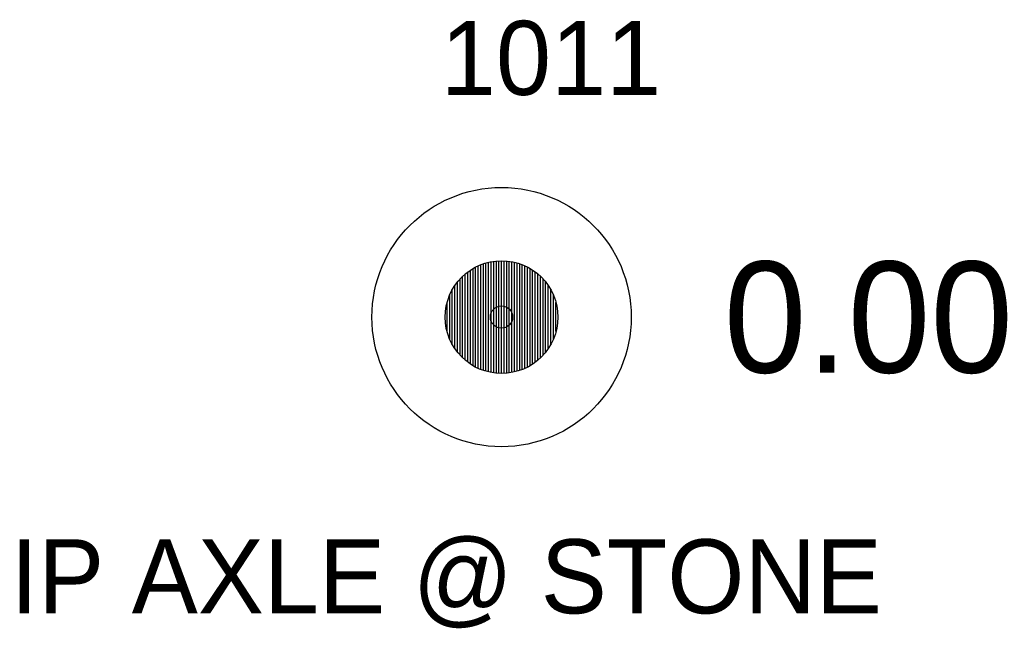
# Model space of a CAD drawing. Extents: x 1393163 to 1398407, y 1072670 to 1074651.
# Drawn here: x 1398094.25 to 1398107.58, y 1074061.18 to 1074069.39 of the extents above; entities that cross this region are included whole.
import ezdxf

# ---------------------------------------------------------------- set-up
doc = ezdxf.new("R2010")
doc.units = 0
for name, color, linetype in [('RD_EX_DV_Prop_txCode', 7, 'Continuous'), ('RD_EX_DV_PropPin', 7, 'Continuous'), ('RD_EX_TX_DV_Prop_ELEV', 7, 'Continuous'), ('RD_SMD_Locator', 7, 'Continuous')]:
    doc.layers.add(name, color=color, linetype=linetype)

msp = doc.modelspace()

# ---------------------------------------------------------------- linework, layer by layer
at = {"layer": 'RD_EX_DV_PropPin'}
for p, q in [((1398100.686, 1074064.619), (1398100.686, 1074066.135)), ((1398100.721, 1074064.617), (1398100.721, 1074066.137)), ((1398100.756, 1074064.616), (1398100.756, 1074066.138)), ((1398100.791, 1074064.617), (1398100.791, 1074066.137)), ((1398100.826, 1074064.619), (1398100.826, 1074066.135)), ((1398100.336, 1074064.742), (1398100.336, 1074066.011)), ((1398100.371, 1074064.721), (1398100.371, 1074066.033)), ((1398100.406, 1074064.701), (1398100.406, 1074066.053)), ((1398100.441, 1074064.684), (1398100.441, 1074066.07)), ((1398100.476, 1074064.669), (1398100.476, 1074066.084)), ((1398100.511, 1074064.656), (1398100.511, 1074066.097)), ((1398100.546, 1074064.645), (1398100.546, 1074066.108)), ((1398100.581, 1074064.636), (1398100.581, 1074066.118)), ((1398100.616, 1074064.629), (1398100.616, 1074066.125)), ((1398100.651, 1074064.623), (1398100.651, 1074066.131)), ((1398100.861, 1074064.623), (1398100.861, 1074066.131)), ((1398100.896, 1074064.629), (1398100.896, 1074066.125)), ((1398100.931, 1074064.636), (1398100.931, 1074066.118)), ((1398100.966, 1074064.645), (1398100.966, 1074066.108)), ((1398101.001, 1074064.656), (1398101.001, 1074066.097)), ((1398101.036, 1074064.669), (1398101.036, 1074066.084)), ((1398101.071, 1074064.684), (1398101.071, 1074066.07)), ((1398101.106, 1074064.701), (1398101.106, 1074066.053)), ((1398101.141, 1074064.721), (1398101.141, 1074066.033)), ((1398101.176, 1074064.742), (1398101.176, 1074066.011)), ((1398100.196, 1074064.862), (1398100.196, 1074065.892)), ((1398100.231, 1074064.826), (1398100.231, 1074065.928)), ((1398100.266, 1074064.795), (1398100.266, 1074065.959)), ((1398100.301, 1074064.767), (1398100.301, 1074065.987)), ((1398101.211, 1074064.767), (1398101.211, 1074065.987)), ((1398101.246, 1074064.795), (1398101.246, 1074065.959)), ((1398101.281, 1074064.826), (1398101.281, 1074065.928)), ((1398101.316, 1074064.862), (1398101.316, 1074065.892)), ((1398100.091, 1074065.007), (1398100.091, 1074065.746)), ((1398100.126, 1074064.95), (1398100.126, 1074065.803)), ((1398100.161, 1074064.903), (1398100.161, 1074065.851)), ((1398101.351, 1074064.903), (1398101.351, 1074065.851)), ((1398101.386, 1074064.95), (1398101.386, 1074065.803)), ((1398101.421, 1074065.007), (1398101.421, 1074065.746)), ((1398100.056, 1074065.079), (1398100.056, 1074065.675)), ((1398101.456, 1074065.079), (1398101.456, 1074065.675)), ((1398100.021, 1074065.181), (1398100.021, 1074065.573)), ((1398101.491, 1074065.181), (1398101.491, 1074065.573))]:
    msp.add_line(p, q, dxfattribs=at)
for radius in [1.75, 0.761]:
    msp.add_circle((1398100.756, 1074065.377), radius, dxfattribs=at)
at = {"layer": 'RD_SMD_Locator'}
msp.add_circle((1398100.756, 1074065.377), 0.15, dxfattribs=at)

# ---------------------------------------------------------------- texts
at = {"layer": 'RD_EX_DV_Prop_txCode'}
for s, p in [('1011', (1398099.937, 1074068.377)), ('IP AXLE @ STONE', (1398094.13, 1074061.377))]:
    msp.add_text(s, height=1, dxfattribs=at).set_placement(p)
at = {"layer": 'RD_EX_TX_DV_Prop_ELEV'}
msp.add_text('0.00', height=1.5, dxfattribs=at).set_placement((1398103.756, 1074064.627))

doc.saveas('drawing.dxf')
